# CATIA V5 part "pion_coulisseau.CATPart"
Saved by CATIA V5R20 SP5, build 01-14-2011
Part number: pion_coulisseau
Bounding box of the stored display mesh (mm): x -445.216 to -435.216, y -27.61 to 15, z -5 to 5
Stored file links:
  F:\iao\catia\projet iao\pion_coulisseau.CATPart
  F:\iao\catia\projet iao\fhartmann.CATProduct
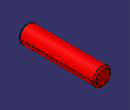
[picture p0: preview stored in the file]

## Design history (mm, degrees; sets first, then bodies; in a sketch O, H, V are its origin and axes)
External parameters (linked from other documents)
  External.coulisseau_largeur = 30 mm
  External.bielle1_epaisseur = 6.61 mm
  External.bielle_diametre_int = 10 mm
Set1
  Plane1: linked copy from another document
  Point1: linked copy from another document
Body1 (main body)
  Sketch1 on Plane1, origin (0, -27.61, 0), H (-1, 0, 0), V (0, 0, 1)
    circle A1 centre (440.2159, 0) radius 5
    point P1 (440.2159, 0)
    reference projected point E1 (440.2159, 0) from Point1
    radius A1 = 5 {= External.bielle_diametre_int /2}
    coincidence: P1 E1
  Pad1: profile Sketch1, direction (0, 1, 0), length 42.61 {= External.coulisseau_largeur +External.bielle1_epaisseur +6mm}
  Chamfer1: length 1, angle 45, on edge [start face of Pad1 | face of Pad1 from Sketch1.A1]; edge [face of Pad1 from Sketch1.A1 | end face of Pad1]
